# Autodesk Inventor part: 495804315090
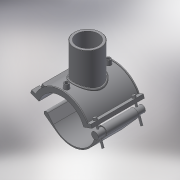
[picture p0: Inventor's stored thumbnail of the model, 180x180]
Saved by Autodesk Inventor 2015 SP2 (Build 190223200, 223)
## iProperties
Created: 2017-07
Part Number: 495804315090
Material: Generic
Description: PLASSON BRANCH SADDLE 315-90
Document SubType Name: Modeling
Designer: KIM
Density: 1 g/cm^3
Appearance: Default
Author: KIM
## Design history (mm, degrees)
derived "495804.ipt"
feature "Solid1::495804.ipt"
feature "Solid2::495804.ipt"
tag "TaggingFeature1"
body "Solid1"
body "Solid2"
other parameters: "d_" = 315, "B_" = 317, "H_" = 105, "L_" = 176, "d_t" = 6, "d1" = 345, "d148" = 7.875, "d160" = 7.875, "d0" = 315, "d2" = 412.1, "d3" = 78.75, "d4" = 176, "d5" = 0, "d6" = 0.1, "d8" = 0, "d19" = 6, "d20" = 6, "d21" = 105.6, "d23" = 0, "d24" = 52.8, "d26" = 0, "d27" = 3, "d28" = 3, "d29" = 3, "d30" = 105, "d31" = 6, "d32" = 0, "d33" = 0, "d34" = 0.6, "d40" = 179.4, "d41" = 99, "d43" = 0, "d45" = 0, "d47" = 277.5, "d50" = 0, "d70" = 15, "d72" = 0, "d73" = 6, "d75" = 5, "d76" = 0, "d77" = 15.75, "d78" = 187.5, "d79" = 15, "d80" = 70.4, "d82" = 5 deg, "d84" = 4, "d85" = 14, "d86" = 0, "d87" = 3, "d88" = 0, "d89" = 1, "d90" = 1, "d91" = 140.8, "d92" = 0, "d93" = 0.5, "d94" = 165.78947, "d96" = 351.9, "d97" = 3.52, "d98" = 0, "d102" = 2.7, "d103" = 72, "d105" = 0, "d109" = -35, "d117" = 0.9, "d120" = 140 deg, "d121" = 24.228, "d122" = 20 deg, "d124" = 207, "d126" = 0, "d143" = 330.75, "d150" = 56.7, "d159" = 6, "d161" = 7.875, "d162" = 105.6, "d163" = 0, "d167" = 63, "d168" = 156.81818, "d173" = 1, "d175" = 157.5, "d176" = 20 deg, "d177" = 22.05, "d178" = 36, "d180" = 0, "d185" = 57.2, "d186" = 57.2, "d187" = 172.5, "d188" = 9, "d189" = 22.05, "d190" = 0, "d191" = 258.75, "d200" = 15, "d202" = 0, "d216" = 158.4, "d217" = 0, "d221" = 65.12, "d222" = 22.05, "d223" = 13.23, "d224" = 157.5, "d225" = 13.23, "d227" = 45.36, "d230" = 187.425, "d236" = 20 deg, "d237" = 181.5, "d238" = 20 deg, "d239" = 22.05
